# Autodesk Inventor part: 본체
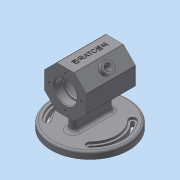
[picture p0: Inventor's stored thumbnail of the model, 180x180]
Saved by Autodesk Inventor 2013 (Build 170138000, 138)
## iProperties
Created: 2017-06
Part Number: 본체
Material: 일반
Document SubType Name: Modeling
Designer: Administrator
Density: 1 g/cm^3
Mass: 207.467 g
Surface Area: 566.157 cm^2
Volume: 207.467 cm^3
Author: Administrator
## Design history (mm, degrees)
sketch "스케치1"
  geometry: C1 r 55 at (0, 0); 2 further points
  constraints: 2 coincident, 1 centre point
  dimensions: "d0" = 110 diameter of C1
extrude "돌출1" new body sketch "스케치1" distance "d2" = 10; taper "d3" = 0 deg
sketch "스케치7" dims "d41" = 60
  geometry: L1 (12.426, 92)-(30, 74.426); L2 (30, 74.426)-(30, 49.574); L3 (30, 49.574)-(12.426, 32); L4 (12.426, 32)-(-12.426, 32); L5 (-12.426, 32)-(-30, 49.574); L6 (-30, 49.574)-(-30, 74.426); L7 (-30, 74.426)-(-12.426, 92); L8 (-12.426, 92)-(12.426, 92); 4 further points
  constraints: 16 end point, 3 vertical alignment, 1 coincident, 1 midpoint, 19 other
  dimensions: "d40" = 62 distance of point (0, 0) point (0, 62)
extrude "돌출5" join sketch "스케치7" stored distance "d42" = 70; taper "d43" = 0 deg
sketch "스케치8"
  geometry: L1 (-35, 92)-(-35, 74.426) reference; L2 (-35, 74.426)-(-35, 49.574) reference; L3 (-35, 49.574)-(-35, 32) reference; L4 (35, 74.426)-(35, 92) reference; L5 (35, 49.574)-(35, 74.426) reference; L6 (35, 32)-(35, 49.574) reference; L7 (-35, 62)-(35, 62); L8 (-35, 78)-(-23, 78); L9 (-23, 78)-(-23, 76); L10 (-23, 76)-(-20, 76); L11 (-20, 76)-(-20, 87); L12 (-20, 87)-(20, 87); L13 (20, 87)-(20, 76); L14 (20, 76)-(23, 76); L15 (23, 76)-(23, 78); L16 (23, 78)-(35, 78); 1 further point
  constraints: 20 end point, 4 collinear, 3 parallel, 2 midpoint, 2 perpendicular, 2 point on line, 2 vertical, 1 horizontal
  dimensions: "d44" = 32 diameter of L8 L7; "d46" = 28 diameter of L10 L7; "d48" = 12 distance of L8.start L8.end; "d49" = 3 distance of L9.end L10.end; "d50" = 50 diameter of L12 L7; "d51" = 40 distance of L11.end L12.end
revolve "회전2" sketch "스케치8" stored, may be unused: angle "d52" = 90 deg
sketch "스케치9" dims "d53" = 46
  geometry: C1 r 16 at (0, 62) reference; 2 further points
  constraints: 2 vertical alignment, 2 other
hole "구멍2" sketch "스케치9" at (0, 85) diameter "d55" = 3.242; stored, may be unused: countersink angle "d59" = 90 deg, drill point angle "d61" = 118 deg; dims "d56" = 8, "d57" = 4, "d58" = 2, "d60" = 10
node "작업 평면2"
sketch "스케치12"
  geometry: L1 (0, 62)-(-26.163, 88.163); L2 (-30, 74.426)-(-12.426, 92) reference; 2 further points
  constraints: 2 end point, 2 vertical alignment, 1 other
  dimensions: "d74" = 45 deg dimension on L1.start L1.end point (0, 76); "d75" = 7 distance from line of L1.end L2
node "작업 평면3"
sketch "스케치13"
  geometry: C1 r 8 at (0, 0); 1 further point
  constraints: 1 centre point
  dimensions: "d76" = 16 diameter of C1
extrude "돌출7" join sketch "스케치13" stored distance "d78" = 70; taper "d79" = 0 deg
sketch "스케치14"
  geometry: C1 r 8 at (0, 0) reference; C2 r 4 at (0, 0); 1 further point
  constraints: 1 centre point
  dimensions: "d80" = 8 diameter of C2
extrude "돌출8" cut sketch "스케치14" stored distance "d82" = 70; taper "d83" = 0 deg
sketch "스케치15"
  geometry: 2 further points
  constraints: 1 coincident, 1 other
feature "엠보싱1" sketch "스케치15" dims "d3" = 0, "d84" = 0.5, "d85" = 0
fillet "모깎기2" dims "d87" = 3
chamfer "모따기1" distance "d88" = 1; stored, may be unused: second distance "d89" = 2, angle "d90" = 45 deg
fillet "모깎기3" dims "d91" = 3
fillet "모깎기4" dims "d92" = 0.3
sketch "스케치16"
  geometry: A1 r 48 centre (0, 0) between (-33.941, 33.941) and (-33.941, -33.941); A2 r 38 centre (0, 0) between (-26.87, 26.87) and (-26.87, -26.87); A3 r 5 centre (-30.406, -30.406) between (-33.941, -33.941) and (-26.87, -26.87); A4 r 5 centre (-30.406, 30.406) between (-26.87, 26.87) and (-33.941, 33.941); 1 further point
  constraints: 8 point on circle, 4 centre point, 4 tangent, 2 horizontal alignment, 1 other
  dimensions: "d93" = 96 diameter of A1; "d95" = 76 diameter of A2; "d96" = 45 deg dimension on A1.centre point (-52, 0) A3.centre; "d97" = 90 deg dimension on A1.centre A4.centre A3.centre
extrude "돌출9" cut sketch "스케치16" distance "d98" = 3; taper "d99" = 0 deg
sketch "스케치17"
  geometry: A1 r 38 centre (0, 0) between (-26.87, 26.87) and (-26.87, -26.87) reference; A2 r 5 centre (-30.406, 30.406) between (-26.87, 26.87) and (-33.941, 33.941) reference; A3 r 48 centre (0, 0) between (-33.941, 33.941) and (-33.941, -33.941) reference; A4 r 5 centre (-30.406, -30.406) between (-33.941, -33.941) and (-26.87, -26.87) reference; A5 r 45 centre (0, 0) between (-31.82, 31.82) and (-31.82, -31.82); A6 r 2 centre (-30.406, 30.406) between (-28.991, 28.991) and (-31.82, 31.82); A7 r 41 centre (0, 0) between (-28.991, 28.991) and (-28.991, -28.991); A8 r 2 centre (-30.406, -30.406) between (-31.82, -31.82) and (-28.991, -28.991)
  constraints: 8 point on circle, 4 centre point, 3 other
  dimensions: "d100" = 2 radius of A6
extrude "돌출10" cut sketch "스케치17" stored distance "d102" = 3; taper "d103" = 0 deg
sketch "스케치18"
  geometry: L1 (-5, -24)-(-5, 24); L2 (5, -24)-(5, 24); A1 r 48 centre (0, 0) between (33.941, -33.941) and (33.941, 33.941) reference; A2 r 5 centre (0, -24) between (-5, -24) and (5, -24); A3 r 5 centre (0, 24) between (5, 24) and (-5, 24)
  constraints: 4 end point, 4 point on circle, 2 centre point, 2 tangent, 2 vertical alignment, 1 equal radius, 1 parallel, 1 vertical
  dimensions: "d104" = 10 diameter of A2; "d106" = 48 distance of A3.centre A2.centre; "d107" = 24 distance of A2.centre A1.centre
extrude "돌출11" join sketch "스케치18" stored distance "d108" = 3; taper "d109" = 0 deg
fillet "모깎기5" dims "d110" = 5
chamfer "모따기2" distance "d111" = 1; stored, may be unused: second distance "d112" = 2, angle "d113" = 45 deg
fillet "모깎기6" dims "d114" = 1
node "솔리드1"
pattern_circular "원형 패턴2" dims angle "d63" = 360 deg
mirror "대칭4"
mirror "대칭5"
